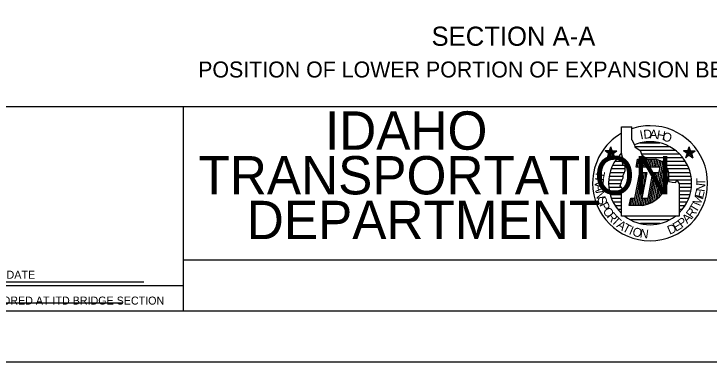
# Model space of a CAD drawing. Extents: x 0 to 22.7, y 0 to 15.7.
# Drawn here: x 8.228 to 12.76, y 0 to 2.271 of the extents above; entities that cross this region are included whole.
import ezdxf

# ---------------------------------------------------------------- set-up
doc = ezdxf.new("R2010")
doc.units = 0
for name, color, linetype in [('BORDER_ANNO_Cutsheet', 7, 'Continuous'), ('BRDG_ANNO_Anno-Large-Print', 7, 'Continuous'), ('BRDG_ANNO_Anno-Sheet', 7, 'Continuous'), ('BRDG_ANNO_Anno-Small-Print', 7, 'Continuous'), ('BRDG_ANNO_General-Notes', 7, 'Continuous')]:
    doc.layers.add(name, color=color, linetype=linetype)

msp = doc.modelspace()

# ---------------------------------------------------------------- linework, layer by layer
at = {"layer": 'BORDER_ANNO_Cutsheet'}
msp.add_lwpolyline([(0, 14.6667), (22.6667, 14.6667), (22.6667, 0), (0, 0)], close=True, dxfattribs=at)
at = {"layer": 'BRDG_ANNO_Anno-Large-Print'}
msp.add_line((7.9329, 0.3871), (8.9371, 0.3871), dxfattribs=at)
at = {"layer": 'BRDG_ANNO_Anno-Sheet'}
for p, q in [((1, 1.6667), (12.8333, 1.6667)), ((9.3333, 0.3333), (9.3333, 1.6667)), ((12.1896, 1.3617), (12.1896, 1.5354)), ((12.1896, 1.5354), (12.2554, 1.5354)), ((12.2554, 1.4487), (12.2554, 1.5354)), ((12.2554, 1.4487), (12.2729, 1.4175)), ((12.2729, 1.4175), (12.2762, 1.4033)), ((12.2779, 1.4054), (12.5004, 1.4054)), ((12.31, 1.4296), (12.4387, 1.4296)), ((12.1342, 1.36), (12.0817, 1.3771)), ((12.1104, 1.3771), (12.0817, 1.3771)), ((12.105, 1.36), (12.0817, 1.3771)), ((12.1288, 1.3771), (12.0958, 1.3321)), ((12.105, 1.36), (12.0958, 1.3321)), ((12.105, 1.36), (12.1579, 1.3771)), ((12.1104, 1.3771), (12.1196, 1.4046)), ((12.1104, 1.3771), (12.1433, 1.3321)), ((12.1196, 1.3492), (12.1196, 1.4046)), ((12.1288, 1.3771), (12.1196, 1.4046)), ((12.1288, 1.3771), (12.1579, 1.3771)), ((12.1342, 1.36), (12.1579, 1.3771)), ((12.1342, 1.36), (12.1433, 1.3321)), ((12.1962, 1.3375), (12.1896, 1.3617)), ((12.2762, 1.4033), (12.3108, 1.3792)), ((12.31, 1.3817), (12.5379, 1.3817)), ((12.3108, 1.3792), (12.3217, 1.3513)), ((12.645, 1.36), (12.5921, 1.3771)), ((12.6158, 1.36), (12.5921, 1.3771)), ((12.6212, 1.3771), (12.5921, 1.3771)), ((12.6396, 1.3771), (12.6067, 1.3321)), ((12.6158, 1.36), (12.6067, 1.3321)), ((12.6158, 1.36), (12.6683, 1.3771)), ((12.6212, 1.3771), (12.6304, 1.4046)), ((12.6212, 1.3771), (12.6542, 1.3321)), ((12.6304, 1.3492), (12.6304, 1.4046)), ((12.6396, 1.3771), (12.6304, 1.4046)), ((12.6396, 1.3771), (12.6683, 1.3771)), ((12.645, 1.36), (12.6683, 1.3771)), ((12.645, 1.36), (12.6542, 1.3321)), ((12.1196, 1.3492), (12.0958, 1.3321)), ((12.1196, 1.3492), (12.1433, 1.3321)), ((12.1612, 1.3337), (12.1958, 1.3337)), ((12.1829, 1.3575), (12.1908, 1.3575)), ((12.1962, 1.3167), (12.1962, 1.3375)), ((12.1962, 1.2992), (12.1962, 1.3167)), ((12.2833, 1.2712), (12.2937, 1.3237)), ((12.2929, 1.2712), (12.3025, 1.3237)), ((12.2937, 1.3237), (12.4083, 1.3237)), ((12.3033, 1.2712), (12.3133, 1.3237)), ((12.3142, 1.2712), (12.3238, 1.3237)), ((12.3192, 1.3575), (12.5671, 1.3575)), ((12.3217, 1.3513), (12.3562, 1.3237)), ((12.3246, 1.2712), (12.3346, 1.3237)), ((12.335, 1.2712), (12.345, 1.3237)), ((12.3438, 1.3337), (12.5883, 1.3337)), ((12.3458, 1.2712), (12.3554, 1.3237)), ((12.3562, 1.2712), (12.3662, 1.3237)), ((12.3671, 1.2712), (12.3767, 1.3237)), ((12.3775, 1.2712), (12.3875, 1.3237)), ((12.3883, 1.2712), (12.3979, 1.3237)), ((12.3987, 1.2712), (12.4087, 1.3237)), ((12.4092, 1.2712), (12.4187, 1.3208)), ((12.42, 1.2712), (12.4287, 1.3179)), ((12.6304, 1.3492), (12.6067, 1.3321)), ((12.6304, 1.3492), (12.6542, 1.3321)), ((12.1312, 1.2854), (12.1988, 1.2854)), ((12.1446, 1.3096), (12.195, 1.3096)), ((12.2, 1.2854), (12.1962, 1.2992)), ((12.2137, 1.2783), (12.2, 1.2854)), ((12.2137, 1.2608), (12.2137, 1.2783)), ((12.4408, 1.2712), (12.2833, 1.2712)), ((12.3996, 1.0496), (12.4479, 1.3079)), ((12.4117, 1.0571), (12.4575, 1.3013)), ((12.4242, 1.0671), (12.4662, 1.2925)), ((12.4304, 1.2712), (12.4383, 1.3133)), ((12.4346, 1.2367), (12.4408, 1.2712)), ((12.4371, 1.0792), (12.475, 1.2829)), ((12.4458, 1.3096), (12.605, 1.3096)), ((12.4504, 1.0933), (12.4833, 1.2708)), ((12.4733, 1.2854), (12.6183, 1.2854)), ((12.1137, 1.2375), (12.2075, 1.2375)), ((12.1208, 1.2617), (12.2125, 1.2617)), ((12.2, 1.2192), (12.2067, 1.2333)), ((12.2067, 1.2333), (12.2137, 1.2504)), ((12.2137, 1.2504), (12.2137, 1.2608)), ((12.2762, 1.07), (12.3075, 1.2367)), ((12.2775, 1.0212), (12.3179, 1.2367)), ((12.2883, 1.0212), (12.3287, 1.2367)), ((12.2988, 1.0212), (12.3392, 1.2367)), ((12.3075, 1.2367), (12.3533, 1.2367)), ((12.3096, 1.0212), (12.35, 1.2367)), ((12.3533, 1.2367), (12.3221, 1.07)), ((12.3625, 1.07), (12.3937, 1.2367)), ((12.3646, 1.0317), (12.4029, 1.2367)), ((12.3758, 1.0367), (12.4133, 1.2367)), ((12.3875, 1.0421), (12.4242, 1.2367)), ((12.3937, 1.2367), (12.4346, 1.2367)), ((12.4646, 1.1125), (12.4912, 1.2546)), ((12.4812, 1.145), (12.4971, 1.23)), ((12.4883, 1.2617), (12.6288, 1.2617)), ((12.4962, 1.2375), (12.6363, 1.2375)), ((12.105, 1.1896), (12.1937, 1.1896)), ((12.1083, 1.2137), (12.1988, 1.2137)), ((12.1858, 1.1671), (12.1896, 1.1812)), ((12.1896, 1.1812), (12.2, 1.2021)), ((12.2, 1.2021), (12.2, 1.2192)), ((12.4938, 1.185), (12.4987, 1.1775)), ((12.495, 1.1896), (12.645, 1.1896)), ((12.4983, 1.2137), (12.6417, 1.2137)), ((12.5404, 1.1708), (12.5508, 1.1846)), ((12.5508, 1.1846), (12.5646, 1.1638)), ((12.1042, 1.1654), (12.185, 1.1654)), ((12.1054, 1.1417), (12.1875, 1.1417)), ((12.1792, 1.15), (12.1858, 1.1671)), ((12.1896, 1.1396), (12.1792, 1.15)), ((12.1962, 1.1292), (12.1896, 1.1396)), ((12.4987, 1.1775), (12.5196, 1.1742)), ((12.5196, 1.1742), (12.5404, 1.1708)), ((12.5633, 1.1654), (12.6458, 1.1654)), ((12.5646, 1.1638), (12.5646, 0.9517)), ((12.565, 1.1417), (12.6446, 1.1417)), ((12.1087, 1.1175), (12.1988, 1.1175)), ((12.1142, 1.0938), (12.1892, 1.0938)), ((12.1896, 1.1013), (12.2, 1.1117)), ((12.1896, 0.9517), (12.1896, 1.1013)), ((12.2, 1.1221), (12.1962, 1.1292)), ((12.2, 1.1117), (12.2, 1.1221)), ((12.5646, 1.1175), (12.6412, 1.1175)), ((12.5646, 1.0938), (12.6358, 1.0938)), ((12.1225, 1.0696), (12.1883, 1.0696)), ((12.1329, 1.0454), (12.1883, 1.0454)), ((12.2396, 1.0212), (12.2487, 1.07)), ((12.2458, 1.0212), (12.255, 1.07)), ((12.2487, 1.07), (12.2762, 1.07)), ((12.2567, 1.0212), (12.2658, 1.07)), ((12.2671, 1.0212), (12.2762, 1.07)), ((12.32, 1.0212), (12.3292, 1.07)), ((12.3221, 1.07), (12.3625, 1.07)), ((12.3308, 1.0217), (12.34, 1.07)), ((12.3421, 1.0246), (12.3504, 1.07)), ((12.3533, 1.0279), (12.3608, 1.07)), ((12.5646, 1.0696), (12.6275, 1.0696)), ((12.5646, 1.0454), (12.6167, 1.0454)), ((12.1467, 1.0217), (12.1887, 1.0217)), ((12.1638, 0.9975), (12.1883, 0.9975)), ((12.3283, 1.0212), (12.2396, 1.0212)), ((12.5646, 1.0217), (12.6033, 1.0217)), ((12.5646, 0.9975), (12.5867, 0.9975)), ((12.185, 0.9738), (12.1892, 0.9738)), ((12.5646, 0.9517), (12.1896, 0.9517)), ((12.5004, 0.9275), (12.2479, 0.9275)), ((12.4392, 0.9037), (12.3117, 0.9037)), ((9.3333, 0.6667), (12.8333, 0.6667))]:
    msp.add_line(p, q, dxfattribs=at)
msp.add_lwpolyline([(1, 14.3333), (22.3333, 14.3333), (22.3333, 0.3333), (1, 0.3333)], close=True, dxfattribs=at)
for centre, radius, start, end in [((12.375, 1.1667), 0.375, 90, 108.596), ((12.375, 1.1667), 0.375, 0, 90), ((12.375, 1.1667), 0.375, 119.6331, 180), ((12.375, 1.1667), 0.2708, 90, 112.1452), ((12.375, 1.1667), 0.2708, 0, 90), ((12.375, 1.1667), 0.2708, 133.1926, 180), ((12.3888, 1.2161), 0.1094, 343.4981, 79.7362), ((12.2899, 1.2255), 0.2078, 280.6479, 348.7719), ((12.375, 1.1667), 0.375, 180, 270), ((12.375, 1.1667), 0.2708, 180.2644, 226.7946), ((12.375, 1.1667), 0.375, 270, 0), ((12.375, 1.1667), 0.2708, 314.427, 0), ((12.375, 1.1667), 0.2708, 232.5658, 270), ((12.375, 1.1667), 0.2708, 270, 307.4536)]:
    msp.add_arc(centre, radius, start, end, dxfattribs=at)
at = {"layer": 'BRDG_ANNO_Anno-Small-Print'}
for p, q in [((7.6667, 0.5), (9.3333, 0.5)), ((8.1442, 0.5242), (9.0758, 0.5242))]:
    msp.add_line(p, q, dxfattribs=at)

# ---------------------------------------------------------------- texts
at = {"layer": 'BRDG_ANNO_Anno-Sheet'}
for s, p in [('IDAHO', (10.2558, 1.3854)), ('TRANSPORTATION', (9.4313, 1.0938)), ('DEPARTMENT', (9.7462, 0.8021))]:
    msp.add_text(s, height=0.25, dxfattribs=at).set_placement(p)
for s, rotation, p in [('I', 11.9519, (12.3146, 1.4521)), ('D', 5.2118, (12.3342, 1.4563)), ('A', 357.8718, (12.3712, 1.4587)), ('H', 349.6318, (12.4146, 1.4558)), ('O', 342.1917, (12.4496, 1.4487)), ('T', 259.4265, (12.0254, 1.2504)), ('R', 266.0275, (12.0175, 1.205)), ('T', 90.4926, (12.7346, 1.1529)), ('A', 273.764, (12.0154, 1.1604)), ('N', 83.1932, (12.73, 1.1087)), ('N', 280.3758, (12.0192, 1.1142)), ('M', 67.7139, (12.7004, 1.0137)), ('E', 75.6105, (12.7196, 1.0646)), ('S', 287.9279, (12.0287, 1.0692)), ('P', 295.4976, (12.0437, 1.0271)), ('O', 302.6446, (12.0637, 0.9867)), ('R', 52.3344, (12.6492, 0.9342)), ('T', 59.0362, (12.6758, 0.97)), ('R', 309.9079, (12.0892, 0.9483)), ('T', 317.1211, (12.1183, 0.9142)), ('A', 45, (12.6171, 0.9004)), ('A', 324.6375, (12.1521, 0.8837)), ('T', 331.7503, (12.1896, 0.8579)), ('E', 30.5476, (12.5437, 0.8492)), ('P', 37.6656, (12.5821, 0.8729)), ('I', 337.0213, (12.2329, 0.8358)), ('O', 343.3287, (12.255, 0.8271)), ('N', 351.6598, (12.3058, 0.8133)), ('D', 22.9887, (12.5021, 0.8304))]:
    msp.add_text(s, height=0.0579, rotation=rotation, dxfattribs=at).set_placement(p)
at = {"layer": 'BRDG_ANNO_Anno-Small-Print'}
for s, height, p in [('DATE', 0.05248, (8.1792, 0.5437)), ('ORIGINAL STORED AT ITD BRIDGE SECTION', 0.052144, (7.7083, 0.3752))]:
    msp.add_text(s, height=height, dxfattribs=at).set_placement(p)
at = {"layer": 'BRDG_ANNO_General-Notes'}
for s, height, p in [('SECTION A-A', 0.124948, (10.9505, 2.0632)), ('POSITION OF LOWER PORTION OF EXPANSION BEARING', 0.104115, (9.4289, 1.8565))]:
    msp.add_text(s, height=height, dxfattribs=at).set_placement(p)

doc.saveas('drawing.dxf')
